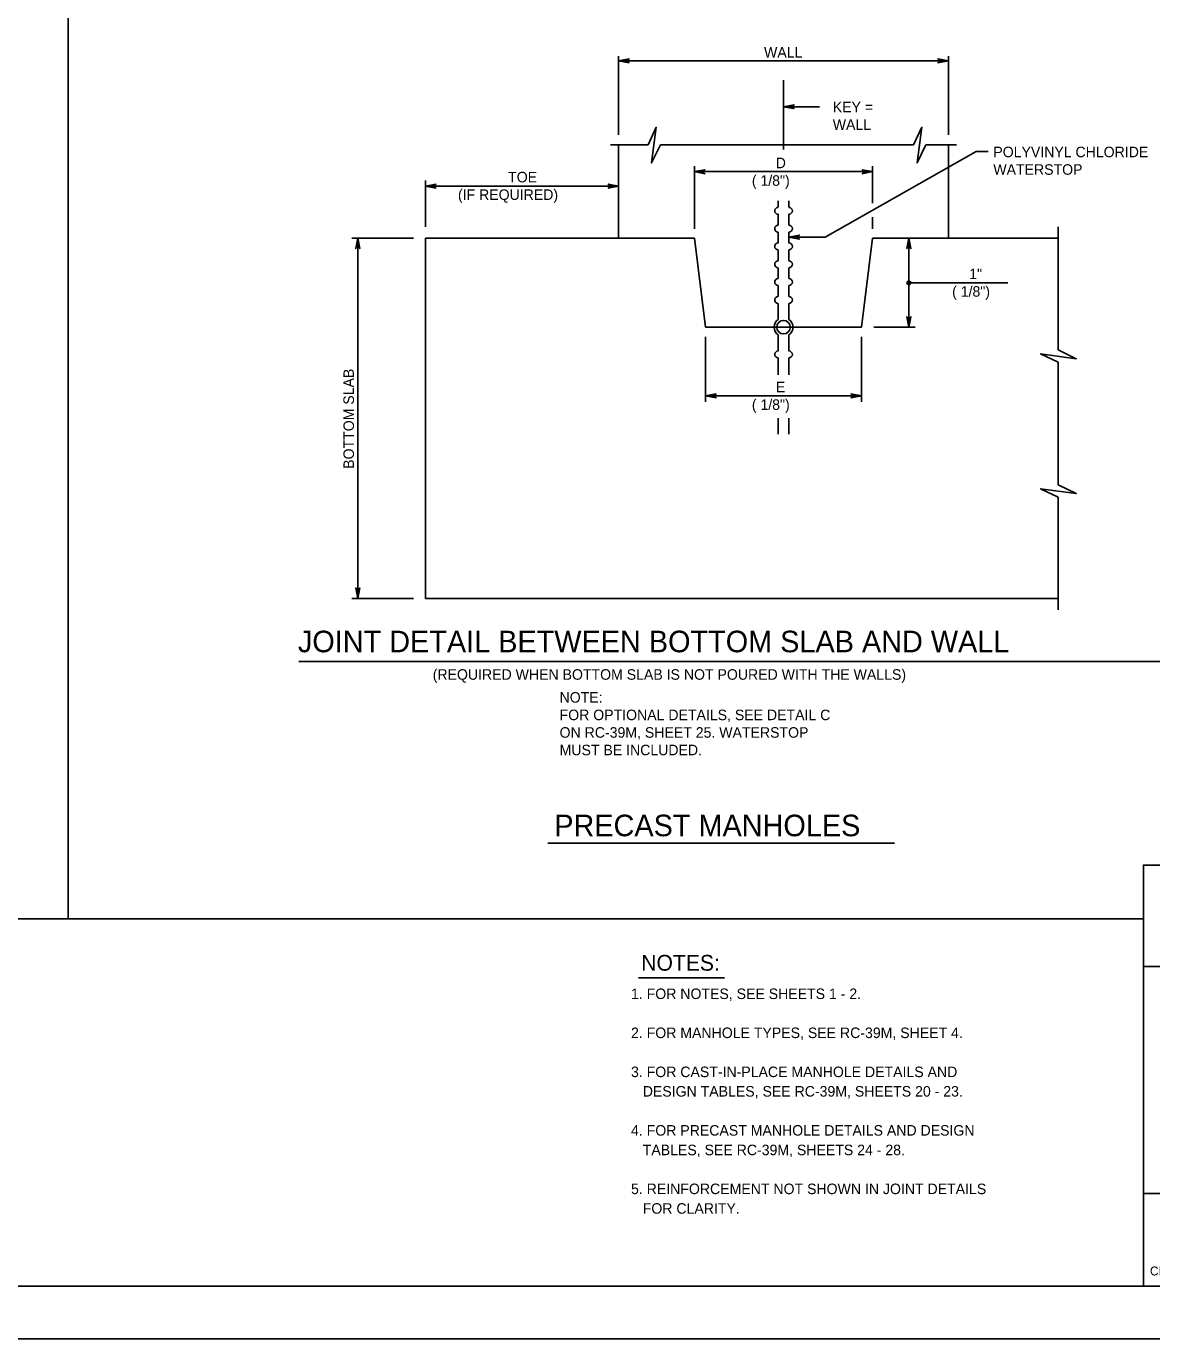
# Model space of a CAD drawing. Extents: x 2106427 to 2114911, y 988717 to 990787.
# Drawn here: x 2112951 to 2114003, y 988839 to 990066 of the extents above; entities that cross this region are included whole.
import ezdxf

# ---------------------------------------------------------------- set-up
doc = ezdxf.new("R2010")
doc.units = 0
for name, color, linetype in [('1', 7, 'Continuous'), ('3', 7, 'Continuous'), ('PLT-BNDY', 7, 'Continuous')]:
    doc.layers.add(name, color=color, linetype=linetype)

msp = doc.modelspace()

# ---------------------------------------------------------------- linework, layer by layer
at = {"layer": '1'}
for p, q in [((2112990.3, 990738.1), (2112990.3, 989231)), ((2113504.9, 990037.7), (2113504.9, 989964)), ((2113504.9, 990033.3), (2113813.1, 990033.3)), ((2113813.1, 990037.7), (2113813.1, 989964)), ((2113659, 989950.3), (2113659, 990015.1)), ((2113659, 989990.3), (2113692.6, 989990.3)), ((2113497.4, 989954.8), (2113532.4, 989954.8)), ((2113504.9, 989954.8), (2113504.9, 989867.5)), ((2113543.9, 989954.8), (2113780.6, 989954.8)), ((2113698, 989868.4), (2113839.1, 989948.4)), ((2113792.1, 989954.8), (2113820.8, 989954.8)), ((2113813.1, 989954.8), (2113813.1, 989867.5)), ((2113839.1, 989948.4), (2113850.4, 989948.4)), ((2113575.7, 989934.6), (2113575.7, 989876.1)), ((2113742.3, 989934.6), (2113742.3, 989900)), ((2113324.3, 989921.3), (2113324.3, 989878)), ((2113575.7, 989929.6), (2113742.3, 989929.6)), ((2113324.3, 989916.1), (2113504.9, 989916.1)), ((2113654, 989896.3), (2113654, 989902.2)), ((2113664, 989896.3), (2113664, 989902.2)), ((2113654, 989879.6), (2113654, 989889.8)), ((2113664, 989879.6), (2113664, 989889.8)), ((2113742.3, 989887.1), (2113742.3, 989876.1)), ((2113654, 989862.9), (2113654, 989873.1)), ((2113664, 989862.9), (2113664, 989873.1)), ((2113915.6, 989763), (2113915.6, 989878.1)), ((2113255.4, 989867.5), (2113313.2, 989867.5)), ((2113261, 989530.7), (2113261, 989867.5)), ((2113324.3, 989867.5), (2113324.3, 989530.7)), ((2113324.3, 989867.5), (2113504.9, 989867.5)), ((2113504.9, 989867.5), (2113575.7, 989867.5)), ((2113586.1, 989784.2), (2113575.7, 989867.5)), ((2113664, 989868.4), (2113698, 989868.4)), ((2113731.9, 989784.2), (2113742.3, 989867.5)), ((2113742.3, 989867.5), (2113915.6, 989867.5)), ((2113776.2, 989867.5), (2113776.2, 989784.2)), ((2113822.7, 989867.5), (2113915.6, 989867.5)), ((2113654, 989846.3), (2113654, 989856.5)), ((2113664, 989846.3), (2113664, 989856.5)), ((2113654, 989829.6), (2113654, 989839.8)), ((2113664, 989829.6), (2113664, 989839.8)), ((2113654, 989812.9), (2113654, 989823.1)), ((2113664, 989812.9), (2113664, 989823.1)), ((2113776.2, 989825.8), (2113868.6, 989825.8)), ((2113654, 989791.4), (2113654, 989806.5)), ((2113664, 989791.4), (2113664, 989806.5)), ((2113586.1, 989784.2), (2113731.9, 989784.2)), ((2113743.5, 989784.2), (2113781.9, 989784.2)), ((2113586.1, 989775.2), (2113586.1, 989714.4)), ((2113654, 989761.9), (2113654, 989776.9)), ((2113664, 989761.9), (2113664, 989776.9)), ((2113731.9, 989775.2), (2113731.9, 989714.4)), ((2113654, 989739.6), (2113654, 989755.4)), ((2113664, 989739.6), (2113664, 989755.4)), ((2113915.6, 989636.9), (2113915.6, 989751.5)), ((2113586.1, 989720), (2113731.9, 989720)), ((2113654, 989684.1), (2113654, 989699.3)), ((2113664, 989684.1), (2113664, 989699.3)), ((2113915.6, 989520.1), (2113915.6, 989625.4)), ((2113255.4, 989530.7), (2113313.2, 989530.7)), ((2113324.3, 989530.7), (2113915.6, 989530.7)), ((2113206, 989471.6), (2114024.1, 989471.6)), ((2113438.8, 989301.9), (2113762.7, 989301.9)), ((2112072.8, 989231), (2113995.4, 989231)), ((2113523.4, 989175.8), (2113603.8, 989175.8))]:
    msp.add_line(p, q, dxfattribs=at)
for points in [[(2114651.6, 988887.7), (2114651.6, 990738.1), (2112072.8, 990738.1), (2112072.8, 988887.7), (2114651.6, 988887.7), (2114651.6, 988974.2), (2113995.4, 988974.2), (2113995.4, 989186.4), (2114651.6, 989186.4), (2114651.6, 989281.4), (2113995.4, 989281.4), (2113995.4, 988887.7), (2114253.9, 988887.7), (2114253.9, 988974.2), (2114253.9, 988887.7), (2114506.6, 988887.7), (2114506.6, 988974.2), (2114506.6, 988933.8), (2114651.6, 988933.8)], [(2113504.9, 990033.3), (2113514.7, 990035.1), (2113514.3, 990034.8), (2113513.9, 990034.6), (2113513.7, 990034.2), (2113513.5, 990033.9), (2113513.5, 990033.6), (2113513.4, 990033.3), (2113513.5, 990032.9), (2113513.5, 990032.6), (2113513.7, 990032.3), (2113513.9, 990031.9), (2113514.3, 990031.7), (2113514.7, 990031.4), (2113504.9, 990033.3), (2113514.3, 990031.7), (2113513.9, 990031.9), (2113504.9, 990033.3), (2113513.7, 990032.3), (2113513.5, 990032.6), (2113504.9, 990033.3), (2113513.5, 990032.9), (2113513.4, 990033.3), (2113504.9, 990033.3), (2113513.5, 990033.6), (2113513.5, 990033.9), (2113504.9, 990033.3), (2113513.7, 990034.2), (2113513.9, 990034.6), (2113504.9, 990033.3), (2113514.3, 990034.8)], [(2113813.1, 990033.3), (2113803.3, 990031.4), (2113803.7, 990031.7), (2113804, 990031.9), (2113804.2, 990032.3), (2113804.4, 990032.6), (2113804.5, 990032.9), (2113804.5, 990033.3), (2113804.5, 990033.6), (2113804.4, 990033.9), (2113804.2, 990034.2), (2113804, 990034.6), (2113803.7, 990034.8), (2113803.3, 990035.1), (2113813.1, 990033.3), (2113803.7, 990034.8), (2113804, 990034.6), (2113813.1, 990033.3), (2113804.2, 990034.2), (2113804.4, 990033.9), (2113813.1, 990033.3), (2113804.5, 990033.6), (2113804.5, 990033.3), (2113813.1, 990033.3), (2113804.5, 990032.9), (2113804.4, 990032.6), (2113813.1, 990033.3), (2113804.2, 990032.3), (2113804, 990031.9), (2113813.1, 990033.3), (2113803.7, 990031.7)], [(2113659, 989990.3), (2113668.8, 989992.2), (2113668.4, 989991.9), (2113668, 989991.6), (2113667.8, 989991.3), (2113667.6, 989991), (2113667.6, 989990.7), (2113667.5, 989990.3), (2113667.6, 989990), (2113667.6, 989989.7), (2113667.8, 989989.3), (2113668, 989989), (2113668.4, 989988.8), (2113668.8, 989988.5), (2113659, 989990.3), (2113668.4, 989988.8), (2113668, 989989), (2113659, 989990.3), (2113667.8, 989989.3), (2113667.6, 989989.7), (2113659, 989990.3), (2113667.6, 989990), (2113667.5, 989990.3), (2113659, 989990.3), (2113667.6, 989990.7), (2113667.6, 989991), (2113659, 989990.3), (2113667.8, 989991.3), (2113668, 989991.6), (2113659, 989990.3), (2113668.4, 989991.9)], [(2113543.9, 989954.8), (2113535.6, 989937.8), (2113540.1, 989971.1), (2113532.4, 989954.8)], [(2113792.1, 989954.8), (2113783.8, 989937.8), (2113788.3, 989971.1), (2113780.6, 989954.8)], [(2113575.7, 989929.6), (2113585.5, 989931.4), (2113585.1, 989931.1), (2113584.7, 989930.9), (2113584.5, 989930.6), (2113584.3, 989930.2), (2113584.3, 989929.9), (2113584.2, 989929.6), (2113584.3, 989929.2), (2113584.3, 989928.9), (2113584.5, 989928.6), (2113584.7, 989928.3), (2113585.1, 989928), (2113585.5, 989927.7), (2113575.7, 989929.6), (2113585.1, 989928), (2113584.7, 989928.3), (2113575.7, 989929.6), (2113584.5, 989928.6), (2113584.3, 989928.9), (2113575.7, 989929.6), (2113584.3, 989929.2), (2113584.2, 989929.6), (2113575.7, 989929.6), (2113584.3, 989929.9), (2113584.3, 989930.2), (2113575.7, 989929.6), (2113584.5, 989930.6), (2113584.7, 989930.9), (2113575.7, 989929.6), (2113585.1, 989931.1)], [(2113742.3, 989929.6), (2113732.5, 989927.7), (2113732.9, 989928), (2113733.3, 989928.3), (2113733.4, 989928.6), (2113733.6, 989928.9), (2113733.7, 989929.2), (2113733.8, 989929.6), (2113733.7, 989929.9), (2113733.6, 989930.2), (2113733.4, 989930.6), (2113733.3, 989930.9), (2113732.9, 989931.1), (2113732.5, 989931.4), (2113742.3, 989929.6), (2113732.9, 989931.1), (2113733.3, 989930.9), (2113742.3, 989929.6), (2113733.4, 989930.6), (2113733.6, 989930.2), (2113742.3, 989929.6), (2113733.7, 989929.9), (2113733.8, 989929.6), (2113742.3, 989929.6), (2113733.7, 989929.2), (2113733.6, 989928.9), (2113742.3, 989929.6), (2113733.4, 989928.6), (2113733.3, 989928.3), (2113742.3, 989929.6), (2113732.9, 989928)], [(2113324.3, 989916.1), (2113334.1, 989917.9), (2113333.3, 989917.4), (2113333, 989916.8), (2113332.8, 989916.1), (2113333, 989915.4), (2113333.3, 989914.8), (2113334.1, 989914.3), (2113324.3, 989916.1), (2113333.3, 989914.8), (2113333, 989915.4), (2113324.3, 989916.1), (2113332.8, 989916.1), (2113333, 989916.8), (2113324.3, 989916.1), (2113333.3, 989917.4)], [(2113504.9, 989916.1), (2113495.1, 989914.3), (2113495.9, 989914.8), (2113496.3, 989915.4), (2113496.4, 989916.1), (2113496.3, 989916.8), (2113495.9, 989917.4), (2113495.1, 989917.9), (2113504.9, 989916.1), (2113495.9, 989917.4), (2113496.3, 989916.8), (2113504.9, 989916.1), (2113496.4, 989916.1), (2113496.3, 989915.4), (2113504.9, 989916.1), (2113495.9, 989914.8)], [(2113664, 989868.4), (2113673.8, 989870.3), (2113673.4, 989870), (2113673, 989869.7), (2113672.8, 989869.4), (2113672.6, 989869.1), (2113672.6, 989868.8), (2113672.5, 989868.4), (2113672.6, 989868.1), (2113672.6, 989867.8), (2113672.8, 989867.4), (2113673, 989867.1), (2113673.4, 989866.9), (2113673.8, 989866.6), (2113664, 989868.4), (2113673.4, 989866.9), (2113673, 989867.1), (2113664, 989868.4), (2113672.8, 989867.4), (2113672.6, 989867.8), (2113664, 989868.4), (2113672.6, 989868.1), (2113672.5, 989868.4), (2113664, 989868.4), (2113672.6, 989868.8), (2113672.6, 989869.1), (2113664, 989868.4), (2113672.8, 989869.4), (2113673, 989869.7), (2113664, 989868.4), (2113673.4, 989870)], [(2113261, 989867.5), (2113262.9, 989857.7), (2113262.6, 989858.1), (2113262.4, 989858.4), (2113262, 989858.6), (2113261.7, 989858.8), (2113261.4, 989858.9), (2113261, 989858.9), (2113260.7, 989858.9), (2113260.4, 989858.8), (2113260.1, 989858.6), (2113259.7, 989858.4), (2113259.5, 989858.1), (2113259.2, 989857.7), (2113261, 989867.5), (2113259.5, 989858.1), (2113259.7, 989858.4), (2113261, 989867.5), (2113260.1, 989858.6), (2113260.4, 989858.8), (2113261, 989867.5), (2113260.7, 989858.9), (2113261, 989858.9), (2113261, 989867.5), (2113261.4, 989858.9), (2113261.7, 989858.8), (2113261, 989867.5), (2113262, 989858.6), (2113262.4, 989858.4), (2113261, 989867.5), (2113262.6, 989858.1)], [(2113776.2, 989867.5), (2113778.1, 989857.7), (2113777.8, 989858.1), (2113777.6, 989858.4), (2113777.2, 989858.6), (2113776.9, 989858.8), (2113776.6, 989858.9), (2113776.2, 989858.9), (2113775.9, 989858.9), (2113775.6, 989858.8), (2113775.3, 989858.6), (2113774.9, 989858.4), (2113774.7, 989858.1), (2113774.4, 989857.7), (2113776.2, 989867.5), (2113774.7, 989858.1), (2113774.9, 989858.4), (2113776.2, 989867.5), (2113775.3, 989858.6), (2113775.6, 989858.8), (2113776.2, 989867.5), (2113775.9, 989858.9), (2113776.2, 989858.9), (2113776.2, 989867.5), (2113776.6, 989858.9), (2113776.9, 989858.8), (2113776.2, 989867.5), (2113777.2, 989858.6), (2113777.6, 989858.4), (2113776.2, 989867.5), (2113777.8, 989858.1)], [(2113776.2, 989784.2), (2113774.4, 989793.9), (2113774.7, 989793.6), (2113774.9, 989793.2), (2113775.3, 989793), (2113775.6, 989792.8), (2113775.9, 989792.8), (2113776.2, 989792.7), (2113776.6, 989792.8), (2113776.9, 989792.8), (2113777.2, 989793), (2113777.6, 989793.2), (2113777.8, 989793.6), (2113778.1, 989793.9), (2113776.2, 989784.2), (2113777.8, 989793.6), (2113777.6, 989793.2), (2113776.2, 989784.2), (2113777.2, 989793), (2113776.9, 989792.8), (2113776.2, 989784.2), (2113776.6, 989792.8), (2113776.2, 989792.7), (2113776.2, 989784.2), (2113775.9, 989792.8), (2113775.6, 989792.8), (2113776.2, 989784.2), (2113775.3, 989793), (2113774.9, 989793.2), (2113776.2, 989784.2), (2113774.7, 989793.6)], [(2113915.6, 989763), (2113932.6, 989754.7), (2113899.3, 989759.2), (2113915.6, 989751.5)], [(2113586.1, 989720), (2113595.9, 989721.8), (2113595.5, 989721.6), (2113595.1, 989721.3), (2113594.9, 989721), (2113594.7, 989720.6), (2113594.7, 989720.3), (2113594.6, 989720), (2113594.7, 989719.7), (2113594.7, 989719.3), (2113594.9, 989719), (2113595.1, 989718.7), (2113595.5, 989718.4), (2113595.9, 989718.2), (2113586.1, 989720), (2113595.5, 989718.4), (2113595.1, 989718.7), (2113586.1, 989720), (2113594.9, 989719), (2113594.7, 989719.3), (2113586.1, 989720), (2113594.7, 989719.7), (2113594.6, 989720), (2113586.1, 989720), (2113594.7, 989720.3), (2113594.7, 989720.6), (2113586.1, 989720), (2113594.9, 989721), (2113595.1, 989721.3), (2113586.1, 989720), (2113595.5, 989721.6)], [(2113731.9, 989720), (2113722.1, 989718.2), (2113722.5, 989718.4), (2113722.9, 989718.7), (2113723, 989719), (2113723.2, 989719.3), (2113723.3, 989719.7), (2113723.4, 989720), (2113723.3, 989720.3), (2113723.2, 989720.6), (2113723, 989721), (2113722.9, 989721.3), (2113722.5, 989721.6), (2113722.1, 989721.8), (2113731.9, 989720), (2113722.5, 989721.6), (2113722.9, 989721.3), (2113731.9, 989720), (2113723, 989721), (2113723.2, 989720.6), (2113731.9, 989720), (2113723.3, 989720.3), (2113723.4, 989720), (2113731.9, 989720), (2113723.3, 989719.7), (2113723.2, 989719.3), (2113731.9, 989720), (2113723, 989719), (2113722.9, 989718.7), (2113731.9, 989720), (2113722.5, 989718.4)], [(2113915.6, 989636.9), (2113932.6, 989628.6), (2113899.3, 989633.2), (2113915.6, 989625.4)], [(2113261, 989530.7), (2113259.2, 989540.5), (2113259.5, 989540.1), (2113259.7, 989539.8), (2113260.1, 989539.6), (2113260.4, 989539.4), (2113260.7, 989539.3), (2113261, 989539.3), (2113261.4, 989539.3), (2113261.7, 989539.4), (2113262, 989539.6), (2113262.4, 989539.8), (2113262.6, 989540.1), (2113262.9, 989540.5), (2113261, 989530.7), (2113262.6, 989540.1), (2113262.4, 989539.8), (2113261, 989530.7), (2113262, 989539.6), (2113261.7, 989539.4), (2113261, 989530.7), (2113261.4, 989539.3), (2113261, 989539.3), (2113261, 989530.7), (2113260.7, 989539.3), (2113260.4, 989539.4), (2113261, 989530.7), (2113260.1, 989539.6), (2113259.7, 989539.8), (2113261, 989530.7), (2113259.5, 989540.1)]]:
    msp.add_lwpolyline(points, dxfattribs=at)
for centre, radius in [((2113776.2, 989825.8), 1.75), ((2113776.2, 989825.8), 1.31), ((2113776.2, 989825.8), 0.875), ((2113776.2, 989825.8), 0.437), ((2113659, 989784.2), 6.34)]:
    msp.add_circle(centre, radius, dxfattribs=at)
for centre, radius, start, end in [((2113654, 989893), 3.24, 90, 270), ((2113664, 989893), 3.24, 270, 90), ((2113654, 989876.4), 3.24, 90, 270), ((2113664, 989876.4), 3.24, 270, 90), ((2113654, 989859.7), 3.24, 90, 270), ((2113664, 989859.7), 3.24, 270, 90), ((2113654, 989843), 3.24, 90, 270), ((2113664, 989843), 3.24, 270, 90), ((2113654, 989826.4), 3.24, 90, 270), ((2113664, 989826.4), 3.24, 270, 90), ((2113654, 989809.7), 3.24, 90, 270), ((2113664, 989809.7), 3.24, 270, 90), ((2113659, 989784.2), 8.83, 124.5073, 235.4927), ((2113659, 989784.2), 8.83, 304.5073, 55.4927), ((2113654, 989758.7), 3.24, 90, 270), ((2113664, 989758.7), 3.24, 270, 90)]:
    msp.add_arc(centre, radius, start, end, dxfattribs=at)
at = {"layer": 'PLT-BNDY'}
msp.add_lwpolyline([(2111944.9, 990787.3), (2114704.1, 990787.3), (2114704.1, 988838.5), (2111944.9, 988838.5)], close=True, dxfattribs=at)

# ---------------------------------------------------------------- texts
at = {"layer": '3'}
for s, height, p in [('WALL', 9.84, (2113640.8, 990036.2)), ('  KEY =', 9.84, (2113697.7, 989985.1)), ('  KEY =', 9.84, (2113697.7, 989985.1)), ('  WALL', 9.84, (2113697.7, 989968.7)), ('  WALL', 9.84, (2113697.7, 989968.7)), ('D', 9.84, (2113651.7, 989932.8)), ('POLYVINYL CHLORIDE', 9.843, (2113855.1, 989943.1)), ('WATERSTOP', 9.84, (2113855.1, 989926.7)), ('TOE', 9.84, (2113401.6, 989919.6)), ('( 1/8")', 9.84, (2113629.4, 989916.4)), ('(IF REQUIRED)', 9.843, (2113354.7, 989903.2)), ('1"', 9.84, (2113832.6, 989829.1)), ('( 1/8")', 9.84, (2113816.6, 989812.7)), ('E', 9.84, (2113651.8, 989723.3)), ('( 1/8")', 9.84, (2113629.4, 989706.9)), ('JOINT DETAIL BETWEEN BOTTOM SLAB AND WALL', 20.158, (2113205.1, 989480.3)), ('(REQUIRED WHEN BOTTOM SLAB IS NOT POURED WITH THE WALLS)', 9.843, (2113331.1, 989454.6)), ('NOTE:', 9.84, (2113449.7, 989433.2)), ('FOR OPTIONAL DETAILS, SEE DETAIL C', 9.843, (2113449.7, 989416.8)), ('ON RC-39M, SHEET 25. WATERSTOP', 9.843, (2113449.7, 989400.4)), ('MUST BE INCLUDED.', 9.843, (2113449.7, 989384)), ('PRECAST MANHOLES', 20.158, (2113444.7, 989308.3)), ('NOTES:', 14.76, (2113526, 989182.6)), (' 1. FOR NOTES, SEE SHEETS 1 - 2.', 9.843, (2113512.8, 989156.1)), (' 2. FOR MANHOLE TYPES, SEE RC-39M, SHEET 4.', 9.843, (2113512.8, 989119.6)), (' 3. FOR CAST-IN-PLACE MANHOLE DETAILS AND', 9.843, (2113512.8, 989083.1)), ('    DESIGN TABLES, SEE RC-39M, SHEETS 20 - 23.', 9.843, (2113512.8, 989064.9)), (' 4. FOR PRECAST MANHOLE DETAILS AND DESIGN', 9.843, (2113512.8, 989028.4)), ('    TABLES, SEE RC-39M, SHEETS 24 - 28.', 9.843, (2113512.8, 989010.1)), (' 5. REINFORCEMENT NOT SHOWN IN JOINT DETAILS', 9.843, (2113512.8, 988973.7)), ('    FOR CLARITY.', 9.843, (2113512.8, 988955.4)), ('CHIEF, HWY. DELIVERY DIVISION', 8.333, (2114001.5, 988897.7))]:
    msp.add_text(s, height=height, dxfattribs=at).set_placement(p)
msp.add_text('BOTTOM SLAB', height=9.843, rotation=90, dxfattribs=at).set_placement((2113257.5, 989651.8))

doc.saveas('drawing.dxf')
